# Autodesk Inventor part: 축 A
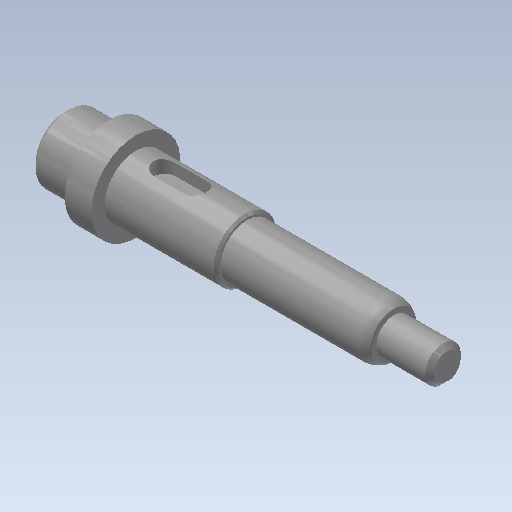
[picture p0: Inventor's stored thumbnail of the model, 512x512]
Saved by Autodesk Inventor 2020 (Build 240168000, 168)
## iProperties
Created: 2020-04
Part Number: 축 A
Material: 강철, 연강
Document SubType Name: Modeling
Designer: mduedu
Density: 7.86 g/cm^3
Mass: 91.1355 g
Surface Area: 41.2026 cm^2
Volume: 11.5948 cm^3
Appearance: 강철
Author: mduedu
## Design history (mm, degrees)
sketch "스케치1"
  geometry: L1 (0, 0)-(10, 0); L2 (10, 0)-(10, 7.5); L3 (10, 7.5)-(0, 7.5); L4 (0, 7.5)-(0, 0); L5 (10, 0)-(16, 0); L6 (16, 0)-(16, 10); L7 (16, 10)-(10, 10); L8 (10, 10)-(10, 0); L9 (16, 0)-(41, 0); L10 (41, 0)-(41, 7); L11 (41, 7)-(16, 7); L12 (16, 7)-(16, 0); L13 (41, 0)-(74, 0); L14 (74, 0)-(74, 6); L15 (74, 6)-(41, 6); L16 (41, 6)-(41, 0); L17 (74, 0)-(86, 0); L18 (86, 0)-(86, 4); L19 (86, 4)-(74, 4); L20 (74, 4)-(74, 0)
  constraints: 40 end point, 10 parallel, 5 horizontal, 5 perpendicular
  dimensions: "d0" = 86 distance between parallel lines of L18 L4; "d2" = 10 distance of L2.end L3.end; "d3" = 6 distance of L6.end L7.end; "d4" = 12 distance of L18.end L19.end; "d5" = 8 diameter of L19 L17; "d6" = 12 diameter of L15 L13; "d7" = 14 diameter of L11 L9; "d8" = 15 diameter of L3 L1; "d9" = 20 diameter of L7 L5; "d10" = 45 distance between parallel lines of L10 L18
revolve "회전1" sketch "스케치1" stored, may be unused: angle "d11" = 90 deg
sketch "스케치2"
  geometry: L1 (0, -7.5)-(0, 7.5) reference; L2 (0, 7.5)-(10, 7.5) reference; L3 (10, 7.5)-(10, 10) reference; L4 (10, 10)-(16, 10) reference; L5 (16, 10)-(16, 7) reference; L6 (16, 7)-(41, 7) reference; L7 (41, 7)-(41, 6) reference; L8 (41, 6)-(74, 6) reference; L9 (74, 6)-(74, 4) reference; L10 (74, 4)-(86, 4) reference; L11 (86, 4)-(86, -4) reference; L12 (86, -4)-(74, -4) reference; L13 (74, -4)-(74, -6) reference; L14 (74, -6)-(41, -6) reference; L15 (41, -6)-(41, -7) reference; L16 (41, -7)-(16, -7) reference; L17 (16, -7)-(16, -10) reference; L18 (16, -10)-(10, -10) reference; L19 (10, -10)-(10, -7.5) reference; L20 (10, -7.5)-(0, -7.5) reference; L21 (86, -4)-(78, -4); L22 (78, -4)-(78, -2.8); L23 (78, -2.8)-(86, -2.8); L24 (86, -2.8)-(86, -4); 1 further point
  constraints: 8 end point, 2 parallel, 1 horizontal, 1 perpendicular
  dimensions: "d12" = 8 distance of L22.end L23.end; "d13" = 1.2 distance of L21.end L22.end
extrude "돌출1" cut sketch "스케치2" stored distance "d14" = 2; taper "d15" = 0 deg
fillet "모깎기1" dims "d16" = 1
sketch "스케치3"
  geometry: L1 (0, -7.5)-(0, 7.5) reference; L2 (0, 7.5)-(10, 7.5) reference; L3 (10, 7.5)-(10, 10) reference; L4 (10, 10)-(16, 10) reference; L5 (16, 10)-(16, 7) reference; L6 (16, 7)-(41, 7) reference; L7 (41, 7)-(41, 6) reference; L8 (41, 6)-(74, 6) reference; L9 (74, 6)-(74, 4) reference; L10 (74, 4)-(86, 4) reference; L11 (86, 4)-(86, -2.8) reference; L12 (86, -2.8)-(78, -2.8) reference; L13 (78, -2.8)-(78, -4) reference; L14 (78, -4)-(74, -4) reference; L15 (74, -4)-(74, -6) reference; L16 (74, -6)-(41, -6) reference; L17 (41, -6)-(41, -7) reference; L18 (41, -7)-(16, -7) reference; L19 (16, -7)-(16, -10) reference; L20 (16, -10)-(10, -10) reference; L21 (10, -10)-(10, -7.5) reference; L22 (10, -7.5)-(0, -7.5) reference; L23 (20, 7)-(32, 7); L24 (32, 7)-(32, 4); L25 (32, 4)-(20, 4); L26 (20, 4)-(20, 7); 1 further point
  constraints: 8 end point, 2 parallel, 1 horizontal, 1 perpendicular, 1 point on line
  dimensions: "d17" = 12 distance of L24.end L25.end; "d18" = 3 distance of L23.end L24.end; "d19" = 4 distance from line of L26 L4.end
extrude "돌출2" cut sketch "스케치3" stored distance "d20" = 5; taper "d21" = 0 deg
fillet "모깎기2" dims "d22" = 2.5
chamfer "모따기1" distance "d23" = 1; stored, may be unused: second distance "d24" = 2, angle "d25" = 45 deg
chamfer "모따기2" distance "d26" = 0.5; stored, may be unused: second distance "d27" = 2, angle "d28" = 45 deg
fillet "모깎기3" dims "d29" = 0.3
chamfer "모따기3" distance "d30" = 1.56; stored, may be unused: second distance "d31" = 2, angle "d32" = 30 deg
fillet "모깎기4" dims "d33" = 4, "d34" = 0.5
node "솔리드1"
node "절단 모서리 투영1"
node "절단 모서리 투영2"
